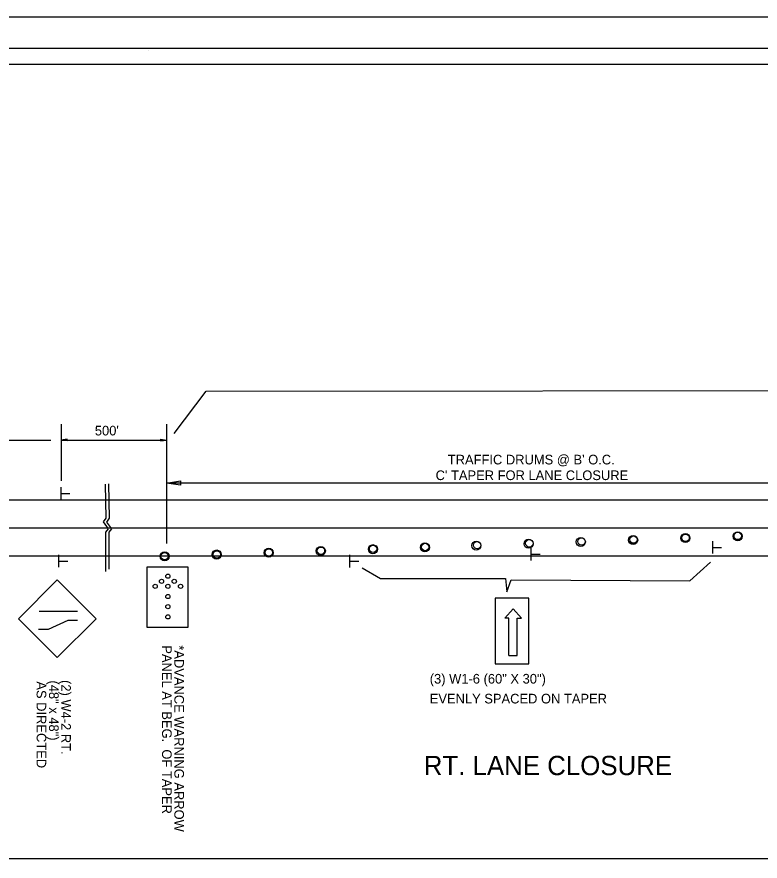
# Model space of a CAD drawing. Extents: x 13528 to 25043, y 7635 to 10612.
# Drawn here: x 16297 to 16759, y 10087 to 10612 of the extents above; entities that cross this region are included whole.
import ezdxf

# ---------------------------------------------------------------- set-up
doc = ezdxf.new("R2010")
doc.units = 0
for name, color, linetype in [('Default', 7, 'Continuous'), ('R_Draft', 7, 'Continuous'), ('R_Revision Date Text', 7, 'Continuous')]:
    doc.layers.add(name, color=color, linetype=linetype)

msp = doc.modelspace()

# ---------------------------------------------------------------- linework, layer by layer
at = {"layer": 'Default'}
for p, q in [((16324.36, 10358.39), (16324.36, 10323.18)), ((16389.83, 10358.39), (16389.83, 10284.25)), ((16265.85, 10348.6), (16318.04, 10348.6)), ((16328.11, 10349.16), (16324.36, 10348.6)), ((16324.36, 10348.6), (16389.83, 10348.6)), ((16328.11, 10348.04), (16324.36, 10348.6)), ((16328.11, 10349.07), (16324.99, 10348.6)), ((16328.11, 10348.13), (16324.99, 10348.6)), ((16328.11, 10348.97), (16325.63, 10348.6)), ((16328.11, 10348.23), (16325.63, 10348.6)), ((16328.11, 10348.88), (16326.26, 10348.6)), ((16328.11, 10348.32), (16326.26, 10348.6)), ((16328.11, 10348.78), (16326.89, 10348.6)), ((16328.11, 10348.42), (16326.89, 10348.6)), ((16328.11, 10348.69), (16327.52, 10348.6)), ((16328.11, 10348.51), (16327.52, 10348.6)), ((16328.11, 10348.04), (16328.11, 10349.16)), ((16386.08, 10349.16), (16389.83, 10348.6)), ((16386.08, 10349.16), (16386.08, 10348.04)), ((16386.08, 10349.07), (16389.21, 10348.6)), ((16386.08, 10348.97), (16388.56, 10348.6)), ((16386.08, 10348.88), (16387.94, 10348.6)), ((16386.08, 10348.78), (16387.3, 10348.6)), ((16386.08, 10348.69), (16386.68, 10348.6)), ((16386.08, 10348.04), (16389.83, 10348.6)), ((16386.08, 10348.42), (16387.3, 10348.6)), ((16386.08, 10348.23), (16388.56, 10348.6)), ((16386.08, 10348.13), (16389.21, 10348.6)), ((16386.08, 10348.32), (16387.94, 10348.6)), ((16386.08, 10348.51), (16386.68, 10348.6)), ((16389.83, 10335.57), (16389.83, 10300.36)), ((16324.36, 10311.44), (16324.36, 10319.27)), ((16389.83, 10321.88), (16398.53, 10323.19)), ((16841.84, 10321.88), (16389.83, 10321.88)), ((16398.53, 10320.58), (16389.83, 10321.88)), ((16398.53, 10323.19), (16398.53, 10320.58)), ((16324.48, 10315.33), (16329.82, 10315.33)), ((16229.91, 10311.48), (16389.83, 10311.48)), ((16389.83, 10311.48), (17102.62, 10311.48)), ((16229.91, 10294.1), (16389.83, 10294.1)), ((16389.83, 10294.1), (17102.62, 10294.1)), ((16729.28, 10278.02), (16729.28, 10285.84)), ((16323.1, 10269.53), (16323.1, 10277.36)), ((16503.86, 10269.49), (16503.86, 10277.31)), ((16616.57, 10273.76), (16616.57, 10281.58)), ((16616.68, 10277.65), (16622.02, 10277.65)), ((16729.39, 10281.91), (16734.73, 10281.91)), ((16229.91, 10276.71), (16389.83, 10276.71)), ((16323.21, 10273.42), (16328.55, 10273.42)), ((16389.83, 10276.71), (17102.62, 10276.71)), ((16503.97, 10273.38), (16509.32, 10273.38)), ((16322.04, 10261.68), (16297.94, 10237.58)), ((16322.04, 10261.68), (16346.13, 10237.58)), ((16310.87, 10242.22), (16334.58, 10242.22)), ((16600.03, 10238.01), (16605.22, 10243.7)), ((16605.22, 10243.7), (16610.41, 10238.01)), ((16297.94, 10237.58), (16322.04, 10213.49)), ((16316.49, 10230.98), (16328.74, 10236.6)), ((16346.13, 10237.58), (16322.04, 10213.49)), ((16328.74, 10236.6), (16334.58, 10236.6)), ((16602.63, 10238.01), (16600.03, 10238.01)), ((16602.63, 10214.71), (16602.63, 10238.01)), ((16607.82, 10214.71), (16607.82, 10238.01)), ((16607.82, 10238.01), (16610.41, 10238.01)), ((16310.36, 10230.98), (16316.49, 10230.98)), ((16602.63, 10214.71), (16607.82, 10214.71))]:
    msp.add_line(p, q, dxfattribs=at)
for points in [[(16394.7, 10352.73), (16414.45, 10378.91), (16832.71, 10379.39), (16840.77, 10403.58), (16841.49, 10379.74), (17088.18, 10376.4), (17099.6, 10350.43)], [(16351.86, 10321.19), (16352.18, 10300.15), (16350.56, 10297.74), (16353.72, 10293.41), (16352.06, 10291.41), (16352.05, 10266.95)], [(16353.86, 10321.38), (16354.18, 10300.07), (16352.56, 10297.66), (16355.72, 10293.33), (16354.06, 10291.33), (16354.05, 10268.36)], [(16511.38, 10269.28), (16522.96, 10262.47), (16600.62, 10262.47), (16601.3, 10254.29), (16604.02, 10261.79), (16715.05, 10261.1), (16728, 10272.69)]]:
    msp.add_lwpolyline(points, dxfattribs=at)
for points in [[(16377.58, 10269.57), (16377.58, 10232.33), (16403.34, 10232.33), (16403.34, 10269.57)], [(16594.09, 10250.36), (16594.09, 10209.5), (16614.99, 10209.5), (16614.99, 10250.36)]]:
    msp.add_lwpolyline(points, close=True, dxfattribs=at)
for centre, radius in [((16647.34, 10285.32), 2.81), ((16647.7, 10285.56), 2.29), ((16679.85, 10286.48), 2.81), ((16680.07, 10286.71), 2.29), ((16712.35, 10287.64), 2.81), ((16712.44, 10287.86), 2.29), ((16744.85, 10288.81), 2.81), ((16744.81, 10289), 2.29), ((16485.78, 10279.67), 2.81), ((16518.12, 10280.78), 2.81), ((16518.23, 10280.97), 2.29), ((16550.45, 10281.89), 2.81), ((16550.6, 10282.12), 2.29), ((16582.34, 10282.99), 2.81), ((16582.97, 10283.27), 2.29), ((16614.84, 10284.15), 2.81), ((16615.34, 10284.42), 2.29), ((16388.78, 10276.35), 2.81), ((16388.64, 10276.4), 2.29), ((16388.76, 10276.39), 2.29), ((16421.11, 10277.46), 2.81), ((16421.13, 10277.53), 2.29), ((16453.45, 10278.56), 2.81), ((16453.5, 10278.68), 2.29), ((16485.86, 10279.83), 2.29), ((16386.81, 10260.83), 1.31), ((16390.75, 10263.99), 1.31), ((16394.7, 10260.83), 1.31), ((16382.86, 10257.67), 1.31), ((16390.75, 10257.67), 1.31), ((16398.65, 10257.67), 1.31), ((16390.75, 10251.34), 1.31), ((16390.75, 10245.02), 1.31), ((16390.75, 10238.7), 1.31)]:
    msp.add_circle(centre, radius, dxfattribs=at)
at = {"layer": 'R_Draft'}
for p, q in [((15615.87, 10592.07), (17196.77, 10592.07)), ((16378.47, 10590.77), (16378.47, 10590.77)), ((16378.47, 10590.77), (16378.47, 10590.77))]:
    msp.add_line(p, q, dxfattribs=at)
at = {"layer": 'R_Revision Date Text'}
for points in [[(15553.84, 10611.55), (17220.54, 10611.55), (17220.54, 9544.86), (15553.84, 9544.86)], [(17186.77, 10088.42), (15625.87, 10088.42), (15625.87, 10582.07), (16873.57, 10582.07), (16873.57, 10532.67), (16961.27, 10532.67), (17081.77, 10532.67), (17081.77, 10421.01), (17186.77, 10421.01)], [(15625.87, 10582.07), (16873.57, 10582.07), (16873.57, 10532.67), (16961.27, 10532.67), (17081.77, 10532.67), (17081.77, 10421.01), (17186.77, 10421.01), (17186.77, 9574.77), (15625.87, 9574.77)]]:
    msp.add_lwpolyline(points, close=True, dxfattribs=at)

# ---------------------------------------------------------------- texts
at = {"layer": 'Default'}
for s, height, p in [("500'", 6, (16345.37, 10351.45)), ("TRAFFIC DRUMS @ B' O.C.", 6, (16564.67, 10333.44)), ("C' TAPER FOR LANE CLOSURE", 6, (16557.11, 10323.71)), ('RT. LANE CLOSURE', 12, (16549.76, 10140.35))]:
    msp.add_text(s, height=height, dxfattribs=at).set_placement(p)
for s, rotation, p in [('PANEL AT BEG.  OF TAPER', 270, (16387.12, 10221.03)), ('*ADVANCE WARNING ARROW', 270, (16394.76, 10221.03)), ('AS DIRECTED ', 270, (16309.18, 10198.64)), ('(48" x 48")', 270, (16316.9, 10199.21)), ('(2) W4-2 RT.', 270, (16324.47, 10199.45)), ('(3) W1-6 (60" X 30")', 0.0075, (16553.47, 10197.25)), ('EVENLY SPACED ON TAPER', 0.0075, (16553.47, 10184.9))]:
    msp.add_text(s, height=6, rotation=rotation, dxfattribs=at).set_placement(p)

doc.saveas('drawing.dxf')
